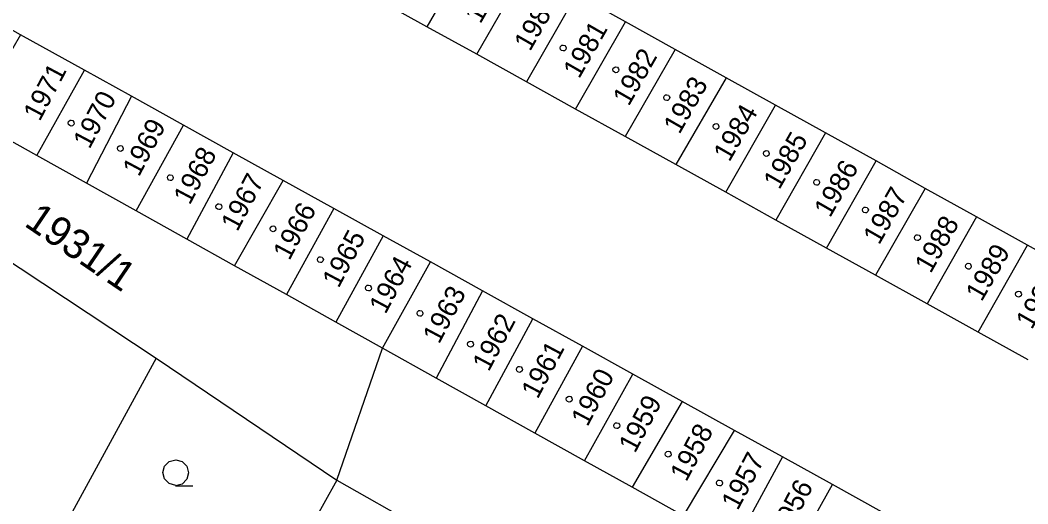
# Model space of a CAD drawing. Extents: x -528274 to -527531, y -1079304 to -1078580.
# Drawn here: x -527957.1 to -527898.8, y -1078698.2 to -1078670.2 of the extents above; entities that cross this region are included whole.
import ezdxf

# ---------------------------------------------------------------- set-up
doc = ezdxf.new("R2010")
doc.units = 0
doc.layers.add('katastrální mapa', color=7, linetype='Continuous')

msp = doc.modelspace()

# ---------------------------------------------------------------- linework, layer by layer
at = {"layer": 'katastrální mapa'}
for p, q in [((-527930.63, -1078665.55), (-527933.53, -1078670.59)), ((-527930.64, -1078672.18), (-527927.75, -1078667.15)), ((-527933.53, -1078670.59), (-527936.56, -1078668.91)), ((-527924.88, -1078668.74), (-527927.77, -1078673.77)), ((-527922.04, -1078670.31), (-527924.88, -1078668.74)), ((-527957.04, -1078671.06), (-527960.16, -1078669.33)), ((-527930.64, -1078672.18), (-527933.53, -1078670.59)), ((-527924.93, -1078675.35), (-527922.04, -1078670.31)), ((-527919.18, -1078671.9), (-527922.04, -1078670.31)), ((-527957.04, -1078671.06), (-527959.85, -1078675.94)), ((-527953.33, -1078673.11), (-527957.04, -1078671.06)), ((-527976.04, -1078672.01), (-527949.18, -1078689.75)), ((-527927.77, -1078673.77), (-527930.64, -1078672.18)), ((-527919.18, -1078671.9), (-527922.06, -1078676.94)), ((-527916.23, -1078673.54), (-527919.18, -1078671.9)), ((-527956.09, -1078678.03), (-527953.33, -1078673.11)), ((-527950.62, -1078674.61), (-527953.33, -1078673.11)), ((-527916.23, -1078673.54), (-527919.13, -1078678.56)), ((-527913.37, -1078675.12), (-527916.23, -1078673.54)), ((-527924.93, -1078675.35), (-527927.77, -1078673.77)), ((-527950.62, -1078674.61), (-527953.21, -1078679.63)), ((-527947.61, -1078676.28), (-527950.62, -1078674.61)), ((-527922.06, -1078676.94), (-527924.93, -1078675.35)), ((-527916.24, -1078680.16), (-527913.37, -1078675.12)), ((-527910.48, -1078676.73), (-527913.37, -1078675.12)), ((-527956.09, -1078678.03), (-527959.85, -1078675.94)), ((-527950.35, -1078681.23), (-527947.61, -1078676.28)), ((-527944.73, -1078677.87), (-527947.61, -1078676.28)), ((-527919.13, -1078678.56), (-527922.06, -1078676.94)), ((-527910.48, -1078676.73), (-527913.35, -1078681.76)), ((-527907.55, -1078678.35), (-527910.48, -1078676.73)), ((-527953.21, -1078679.63), (-527956.09, -1078678.03)), ((-527944.73, -1078677.87), (-527947.41, -1078682.86)), ((-527941.84, -1078679.47), (-527944.73, -1078677.87)), ((-527916.24, -1078680.16), (-527919.13, -1078678.56)), ((-527910.42, -1078683.38), (-527907.55, -1078678.35)), ((-527904.71, -1078679.93), (-527907.55, -1078678.35)), ((-527950.35, -1078681.23), (-527953.21, -1078679.63)), ((-527944.66, -1078684.4), (-527941.84, -1078679.47)), ((-527938.91, -1078681.09), (-527941.84, -1078679.47)), ((-527904.71, -1078679.93), (-527907.58, -1078684.95)), ((-527901.74, -1078681.57), (-527904.71, -1078679.93)), ((-527913.35, -1078681.76), (-527916.24, -1078680.16)), ((-527938.91, -1078681.09), (-527941.65, -1078686.07)), ((-527936.06, -1078682.67), (-527938.91, -1078681.09)), ((-527947.41, -1078682.86), (-527950.35, -1078681.23)), ((-527910.42, -1078683.38), (-527913.35, -1078681.76)), ((-527901.74, -1078681.57), (-527904.6, -1078686.6)), ((-527898.8, -1078683.21), (-527901.74, -1078681.57)), ((-527944.66, -1078684.4), (-527947.41, -1078682.86)), ((-527936.06, -1078682.67), (-527938.8, -1078687.66)), ((-527933.32, -1078684.18), (-527936.06, -1078682.67)), ((-527907.58, -1078684.95), (-527910.42, -1078683.38)), ((-527901.65, -1078688.23), (-527898.8, -1078683.21)), ((-527895.89, -1078684.82), (-527898.8, -1078683.21)), ((-527941.65, -1078686.07), (-527944.66, -1078684.4)), ((-527936.09, -1078689.17), (-527933.32, -1078684.18)), ((-527930.31, -1078685.85), (-527933.32, -1078684.18)), ((-527904.6, -1078686.6), (-527907.58, -1078684.95)), ((-527930.31, -1078685.85), (-527932.99, -1078690.89)), ((-527927.4, -1078687.46), (-527930.31, -1078685.85)), ((-527938.8, -1078687.66), (-527941.65, -1078686.07)), ((-527901.65, -1078688.23), (-527904.6, -1078686.6)), ((-527930.12, -1078692.49), (-527927.4, -1078687.46)), ((-527924.54, -1078689.04), (-527927.4, -1078687.46)), ((-527936.09, -1078689.17), (-527938.8, -1078687.66)), ((-527898.75, -1078689.84), (-527901.65, -1078688.23)), ((-527938.74, -1078696.78), (-527936.09, -1078689.17)), ((-527932.99, -1078690.89), (-527936.09, -1078689.17)), ((-527924.54, -1078689.04), (-527927.29, -1078694.07)), ((-527921.62, -1078690.66), (-527924.54, -1078689.04)), ((-527949.18, -1078689.75), (-527974.26, -1078735.45)), ((-527949.18, -1078689.75), (-527938.74, -1078696.78)), ((-527930.12, -1078692.49), (-527932.99, -1078690.89)), ((-527924.41, -1078695.67), (-527921.62, -1078690.66)), ((-527918.76, -1078692.24), (-527921.62, -1078690.66)), ((-527918.76, -1078692.24), (-527921.66, -1078697.2)), ((-527915.74, -1078693.91), (-527918.76, -1078692.24)), ((-527927.29, -1078694.07), (-527930.12, -1078692.49)), ((-527918.69, -1078698.85), (-527915.74, -1078693.91)), ((-527912.96, -1078695.45), (-527915.74, -1078693.91)), ((-527924.41, -1078695.67), (-527927.29, -1078694.07)), ((-527921.66, -1078697.2), (-527924.41, -1078695.67)), ((-527912.96, -1078695.45), (-527915.72, -1078700.51)), ((-527910.08, -1078697.04), (-527912.96, -1078695.45)), ((-527938.74, -1078696.78), (-527955.27, -1078726.39)), ((-527938.74, -1078696.78), (-527928.49, -1078702.57)), ((-527918.69, -1078698.85), (-527921.66, -1078697.2)), ((-527912.91, -1078702.07), (-527910.08, -1078697.04)), ((-527907.2, -1078698.64), (-527910.08, -1078697.04))]:
    msp.add_line(p, q, dxfattribs=at)
for points in [[(-527925.65, -1078671.65), (-527925.55, -1078671.67), (-527925.5, -1078671.76), (-527925.48, -1078671.82), (-527925.5, -1078671.91), (-527925.58, -1078671.98), (-527925.65, -1078671.99), (-527925.74, -1078671.96), (-527925.8, -1078671.9), (-527925.82, -1078671.82), (-527925.8, -1078671.73), (-527925.72, -1078671.66)], [(-527922.6, -1078672.91), (-527922.5, -1078672.93), (-527922.45, -1078673.02), (-527922.43, -1078673.08), (-527922.45, -1078673.17), (-527922.53, -1078673.24), (-527922.6, -1078673.25), (-527922.69, -1078673.22), (-527922.75, -1078673.16), (-527922.77, -1078673.08), (-527922.75, -1078672.99), (-527922.67, -1078672.92)], [(-527919.66, -1078674.52), (-527919.56, -1078674.54), (-527919.51, -1078674.63), (-527919.49, -1078674.69), (-527919.51, -1078674.78), (-527919.59, -1078674.85), (-527919.66, -1078674.86), (-527919.75, -1078674.83), (-527919.81, -1078674.77), (-527919.83, -1078674.69), (-527919.81, -1078674.6), (-527919.73, -1078674.53)], [(-527954.1, -1078675.99), (-527954, -1078676.01), (-527953.95, -1078676.1), (-527953.93, -1078676.16), (-527953.95, -1078676.25), (-527954.03, -1078676.32), (-527954.1, -1078676.33), (-527954.19, -1078676.3), (-527954.25, -1078676.24), (-527954.27, -1078676.16), (-527954.25, -1078676.07), (-527954.17, -1078676)], [(-527916.81, -1078676.19), (-527916.71, -1078676.21), (-527916.66, -1078676.3), (-527916.64, -1078676.36), (-527916.66, -1078676.45), (-527916.74, -1078676.52), (-527916.81, -1078676.53), (-527916.9, -1078676.5), (-527916.96, -1078676.44), (-527916.98, -1078676.36), (-527916.96, -1078676.27), (-527916.88, -1078676.2)], [(-527951.26, -1078677.46), (-527951.16, -1078677.48), (-527951.11, -1078677.57), (-527951.09, -1078677.63), (-527951.11, -1078677.72), (-527951.19, -1078677.79), (-527951.26, -1078677.8), (-527951.35, -1078677.77), (-527951.41, -1078677.71), (-527951.43, -1078677.63), (-527951.41, -1078677.54), (-527951.33, -1078677.47)], [(-527913.9, -1078677.75), (-527913.8, -1078677.77), (-527913.75, -1078677.86), (-527913.73, -1078677.92), (-527913.75, -1078678.01), (-527913.83, -1078678.08), (-527913.9, -1078678.09), (-527913.99, -1078678.06), (-527914.05, -1078678), (-527914.07, -1078677.92), (-527914.05, -1078677.83), (-527913.97, -1078677.76)], [(-527948.37, -1078679.14), (-527948.27, -1078679.16), (-527948.22, -1078679.25), (-527948.2, -1078679.31), (-527948.22, -1078679.4), (-527948.3, -1078679.47), (-527948.37, -1078679.48), (-527948.46, -1078679.45), (-527948.52, -1078679.39), (-527948.54, -1078679.31), (-527948.52, -1078679.22), (-527948.44, -1078679.15)], [(-527910.99, -1078679.41), (-527910.89, -1078679.43), (-527910.84, -1078679.52), (-527910.82, -1078679.58), (-527910.84, -1078679.67), (-527910.92, -1078679.74), (-527910.99, -1078679.75), (-527911.08, -1078679.72), (-527911.14, -1078679.66), (-527911.16, -1078679.58), (-527911.14, -1078679.49), (-527911.06, -1078679.42)], [(-527945.56, -1078680.82), (-527945.46, -1078680.84), (-527945.41, -1078680.93), (-527945.39, -1078680.99), (-527945.41, -1078681.08), (-527945.49, -1078681.15), (-527945.56, -1078681.16), (-527945.65, -1078681.13), (-527945.71, -1078681.07), (-527945.73, -1078680.99), (-527945.71, -1078680.9), (-527945.63, -1078680.83)], [(-527908.17, -1078681.01), (-527908.07, -1078681.03), (-527908.02, -1078681.12), (-527908, -1078681.18), (-527908.02, -1078681.27), (-527908.1, -1078681.34), (-527908.17, -1078681.35), (-527908.26, -1078681.32), (-527908.32, -1078681.26), (-527908.34, -1078681.18), (-527908.32, -1078681.09), (-527908.24, -1078681.02)], [(-527942.43, -1078682.1), (-527942.33, -1078682.12), (-527942.28, -1078682.21), (-527942.26, -1078682.27), (-527942.28, -1078682.36), (-527942.36, -1078682.43), (-527942.43, -1078682.44), (-527942.52, -1078682.41), (-527942.58, -1078682.35), (-527942.6, -1078682.27), (-527942.58, -1078682.18), (-527942.5, -1078682.11)], [(-527905.16, -1078682.61), (-527905.06, -1078682.63), (-527905.01, -1078682.72), (-527904.99, -1078682.78), (-527905.01, -1078682.87), (-527905.09, -1078682.94), (-527905.16, -1078682.95), (-527905.25, -1078682.92), (-527905.31, -1078682.86), (-527905.33, -1078682.78), (-527905.31, -1078682.69), (-527905.23, -1078682.62)], [(-527939.69, -1078683.88), (-527939.59, -1078683.9), (-527939.54, -1078683.99), (-527939.52, -1078684.05), (-527939.54, -1078684.14), (-527939.62, -1078684.21), (-527939.69, -1078684.22), (-527939.78, -1078684.19), (-527939.84, -1078684.13), (-527939.86, -1078684.05), (-527939.84, -1078683.96), (-527939.76, -1078683.89)], [(-527902.22, -1078684.26), (-527902.12, -1078684.28), (-527902.07, -1078684.37), (-527902.05, -1078684.43), (-527902.07, -1078684.52), (-527902.15, -1078684.59), (-527902.22, -1078684.6), (-527902.31, -1078684.57), (-527902.37, -1078684.51), (-527902.39, -1078684.43), (-527902.37, -1078684.34), (-527902.29, -1078684.27)], [(-527936.91, -1078685.52), (-527936.81, -1078685.54), (-527936.76, -1078685.63), (-527936.74, -1078685.69), (-527936.76, -1078685.78), (-527936.84, -1078685.85), (-527936.91, -1078685.86), (-527937, -1078685.83), (-527937.06, -1078685.77), (-527937.08, -1078685.69), (-527937.06, -1078685.6), (-527936.98, -1078685.53)], [(-527899.32, -1078685.87), (-527899.22, -1078685.89), (-527899.17, -1078685.98), (-527899.15, -1078686.04), (-527899.17, -1078686.13), (-527899.25, -1078686.2), (-527899.32, -1078686.21), (-527899.41, -1078686.18), (-527899.47, -1078686.12), (-527899.49, -1078686.04), (-527899.47, -1078685.95), (-527899.39, -1078685.88)], [(-527933.93, -1078686.98), (-527933.83, -1078687), (-527933.78, -1078687.09), (-527933.76, -1078687.15), (-527933.78, -1078687.24), (-527933.86, -1078687.31), (-527933.93, -1078687.32), (-527934.02, -1078687.29), (-527934.08, -1078687.23), (-527934.1, -1078687.15), (-527934.08, -1078687.06), (-527934, -1078686.99)], [(-527931.01, -1078688.76), (-527930.91, -1078688.78), (-527930.86, -1078688.87), (-527930.84, -1078688.93), (-527930.86, -1078689.02), (-527930.94, -1078689.09), (-527931.01, -1078689.1), (-527931.1, -1078689.07), (-527931.16, -1078689.01), (-527931.18, -1078688.93), (-527931.16, -1078688.84), (-527931.08, -1078688.77)], [(-527928.18, -1078690.22), (-527928.08, -1078690.24), (-527928.03, -1078690.33), (-527928.01, -1078690.39), (-527928.03, -1078690.48), (-527928.11, -1078690.55), (-527928.18, -1078690.56), (-527928.27, -1078690.53), (-527928.33, -1078690.47), (-527928.35, -1078690.39), (-527928.33, -1078690.3), (-527928.25, -1078690.23)], [(-527925.3, -1078691.94), (-527925.2, -1078691.96), (-527925.15, -1078692.05), (-527925.13, -1078692.11), (-527925.15, -1078692.2), (-527925.23, -1078692.27), (-527925.3, -1078692.28), (-527925.39, -1078692.25), (-527925.45, -1078692.19), (-527925.47, -1078692.11), (-527925.45, -1078692.02), (-527925.37, -1078691.95)], [(-527922.55, -1078693.47), (-527922.45, -1078693.49), (-527922.4, -1078693.58), (-527922.38, -1078693.64), (-527922.4, -1078693.73), (-527922.48, -1078693.8), (-527922.55, -1078693.81), (-527922.64, -1078693.78), (-527922.7, -1078693.72), (-527922.72, -1078693.64), (-527922.7, -1078693.55), (-527922.62, -1078693.48)], [(-527919.58, -1078695.12), (-527919.48, -1078695.14), (-527919.43, -1078695.23), (-527919.41, -1078695.29), (-527919.43, -1078695.38), (-527919.51, -1078695.45), (-527919.58, -1078695.46), (-527919.67, -1078695.43), (-527919.73, -1078695.37), (-527919.75, -1078695.29), (-527919.73, -1078695.2), (-527919.65, -1078695.13)], [(-527916.61, -1078696.78), (-527916.51, -1078696.8), (-527916.46, -1078696.89), (-527916.44, -1078696.95), (-527916.46, -1078697.04), (-527916.54, -1078697.11), (-527916.61, -1078697.12), (-527916.7, -1078697.09), (-527916.76, -1078697.03), (-527916.78, -1078696.95), (-527916.76, -1078696.86), (-527916.68, -1078696.79)]]:
    msp.add_lwpolyline(points, close=True, dxfattribs=at)
msp.add_lwpolyline([(-527948.05, -1078697.09), (-527948.43, -1078696.99), (-527948.7, -1078696.72), (-527948.8, -1078696.35), (-527948.7, -1078695.98), (-527948.43, -1078695.71), (-527948.06, -1078695.61), (-527947.69, -1078695.71), (-527947.42, -1078695.98), (-527947.32, -1078696.36), (-527947.42, -1078696.74), (-527947.69, -1078697.01), (-527948.07, -1078697.11), (-527947.07, -1078697.11)], dxfattribs=at)

# ---------------------------------------------------------------- texts
for s, height, rotation, p in [('1979', 1.14, 60.16057, (-527930.439, -1078670.472)), ('1980', 1.14, 60.16057, (-527927.569, -1078672.062)), ('1981', 1.14, 60.16057, (-527924.729, -1078673.642)), ('1982', 1.14, 60.16057, (-527921.859, -1078675.232)), ('1971', 1.14, 62.05133, (-527955.927, -1078676.107)), ('1983', 1.14, 60.16057, (-527918.929, -1078676.852)), ('1970', 1.14, 62.05133, (-527953.047, -1078677.707)), ('1984', 1.14, 60.16057, (-527916.039, -1078678.452)), ('1969', 1.14, 62.05133, (-527950.187, -1078679.307)), ('1985', 1.14, 60.16057, (-527913.149, -1078680.052)), ('1968', 1.14, 62.05133, (-527947.247, -1078680.937)), ('1986', 1.14, 60.16057, (-527910.219, -1078681.672)), ('1967', 1.14, 62.05133, (-527944.497, -1078682.477)), ('1987', 1.14, 60.16057, (-527907.379, -1078683.242)), ('1931/1', 1.7, 325.8411, (-527956.885, -1078682.06)), ('1966', 1.14, 62.05133, (-527941.487, -1078684.147)), ('1988', 1.14, 60.16057, (-527904.399, -1078684.892)), ('1965', 1.14, 62.05133, (-527938.637, -1078685.737)), ('1989', 1.14, 60.16057, (-527901.449, -1078686.522)), ('1964', 1.14, 62.05133, (-527935.927, -1078687.247)), ('1990', 1.14, 60.16057, (-527898.549, -1078688.132)), ('1963', 1.14, 62.05133, (-527932.827, -1078688.967)), ('1962', 1.14, 62.05133, (-527929.957, -1078690.567)), ('1961', 1.14, 62.05133, (-527927.127, -1078692.147)), ('1960', 1.14, 62.05133, (-527924.247, -1078693.747)), ('1959', 1.14, 62.05133, (-527921.497, -1078695.277)), ('1958', 1.14, 62.05133, (-527918.527, -1078696.927)), ('1957', 1.14, 62.05133, (-527915.557, -1078698.587)), ('1956', 1.14, 62.05133, (-527912.747, -1078700.147))]:
    msp.add_text(s, height=height, rotation=rotation, dxfattribs=at).set_placement(p)

doc.saveas('drawing.dxf')
